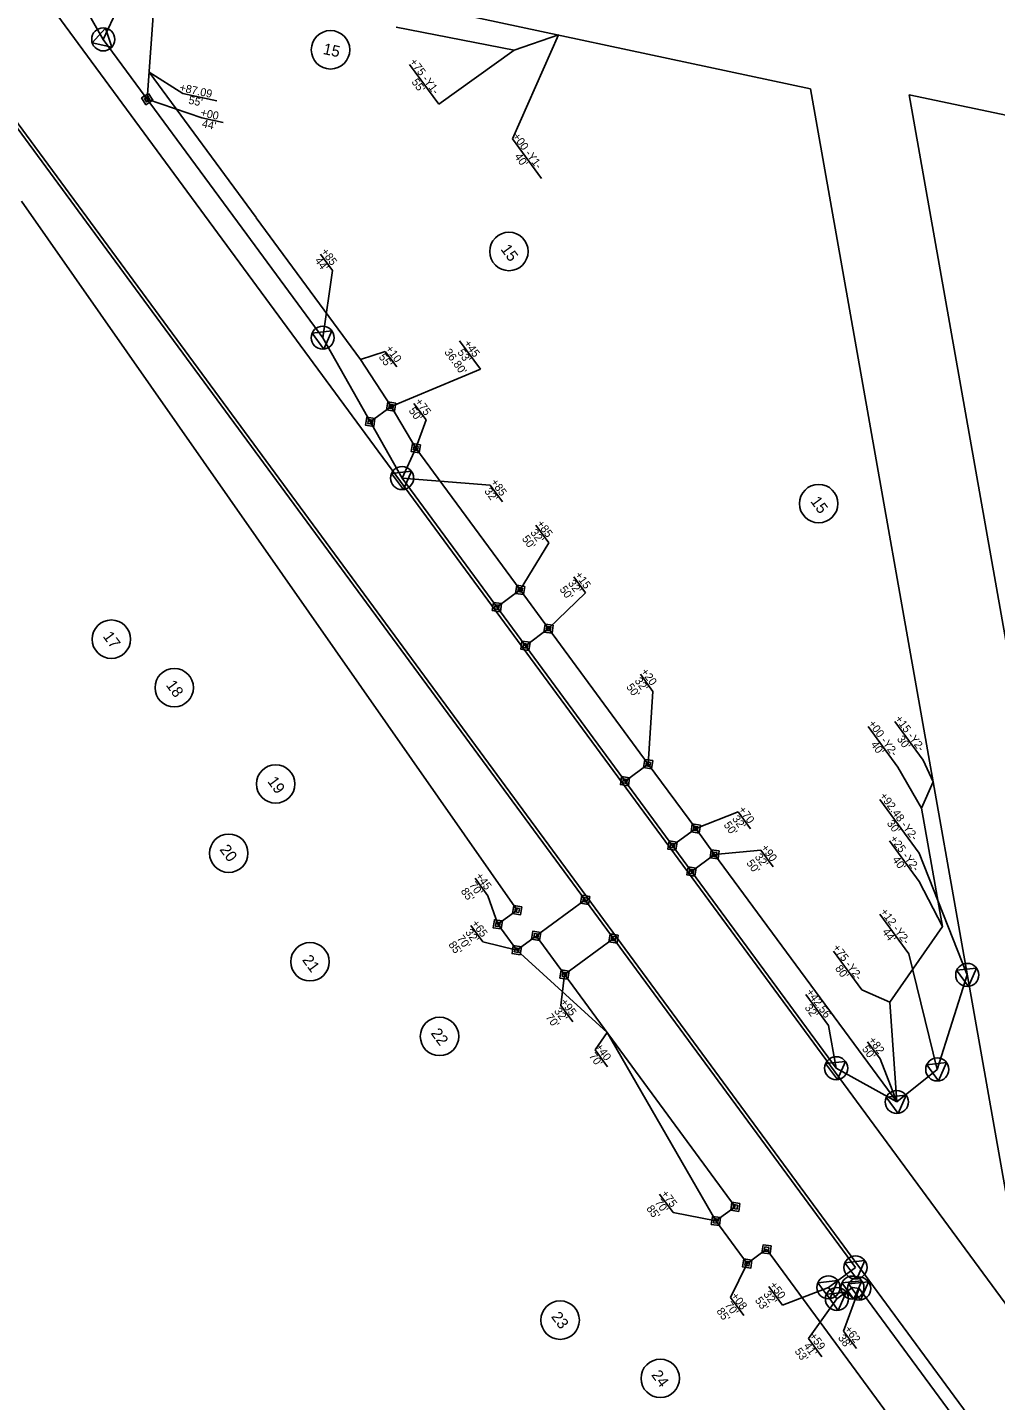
# Model space of a CAD drawing. Extents: x 1762160 to 1765875, y 710174 to 712931.
# Drawn here: x 1763351 to 1763955, y 711555 to 712412 of the extents above; entities that cross this region are included whole.
import ezdxf

# ---------------------------------------------------------------- set-up
doc = ezdxf.new("R2010")
doc.units = 0
for name, color, linetype in [('Exist Building', 7, 'Continuous'), ('Exist Building Foundations', 7, 'Continuous'), ('Exist Other Culture Area Outline', 7, 'Continuous'), ('Exist Other Culture Fence Line', 7, 'Continuous'), ('Exist Other Culture Located Object CELL', 7, 'Continuous'), ('Exist Other Culture Sign CELL', 7, 'Continuous'), ('Exist Roads Curbs', 7, 'Continuous'), ('Exist Roads EOP Other', 7, 'Continuous'), ('Exist Roads Soil', 7, 'Continuous'), ('Exist Structure Minor Head and End Wall', 7, 'Continuous'), ('Exist Utilities Other Pole CELL', 7, 'Continuous'), ('Exist Utilities Other Pole With Base CELL', 7, 'Continuous'), ('Exist Vegetation Shrub CELL', 7, 'Continuous'), ('Exist Vegetation Tree CELL', 7, 'Continuous'), ('Exist Vegetation Woods Line', 7, 'Continuous')]:
    doc.layers.add(name, color=color, linetype=linetype)

msp = doc.modelspace()

# ---------------------------------------------------------------- linework, layer by layer
at = {"layer": 'Exist Building'}
for p, q in [((1763658.25, 712060.86), (1763643.74, 712050.2)), ((1763658.25, 712060.86), (1763676.02, 712036.69)), ((1763676.02, 712036.69), (1763661.52, 712026.03)), ((1763738.22, 711952.1), (1763723.71, 711941.44)), ((1763738.22, 711952.1), (1763767.83, 711911.81))]:
    msp.add_line(p, q, dxfattribs=at)
at = {"layer": 'Exist Building Foundations'}
for p, q in [((1763430.66, 712441.3), (1763425.35, 712367.49)), ((1763346.94, 712303.63), (1763656.35, 711860.87)), ((1763564.68, 712165.84), (1763577.73, 712175.43)), ((1763577.73, 712175.43), (1763593.09, 712149.49)), ((1763593.09, 712149.49), (1763584.51, 712130.77)), ((1763767.83, 711911.81), (1763779.68, 711895.7)), ((1763779.68, 711895.7), (1763765.18, 711885.04)), ((1763644.26, 711851.99), (1763656.35, 711860.87)), ((1763644.26, 711851.99), (1763656.11, 711835.87)), ((1763656.11, 711835.87), (1763667.77, 711844.45)), ((1763685.96, 711820.59), (1763792.59, 711675.57)), ((1763780.5, 711666.68), (1763792.59, 711675.57)), ((1763780.5, 711666.68), (1763800.05, 711640.1)), ((1763800.05, 711640.1), (1763812.14, 711648.98)), ((1763812.14, 711648.98), (1763911.06, 711514.43))]:
    msp.add_line(p, q, dxfattribs=at)
at = {"layer": 'Exist Other Culture Area Outline'}
for p, q in [((1763397.92, 712404.8), (1763424.78, 712462.47)), ((1763397.92, 712404.8), (1763484.59, 712286.92)), ((1763336.69, 712359.78), (1763423.36, 712241.91)), ((1763484.59, 712286.92), (1763534.94, 712218.44)), ((1763423.36, 712241.91), (1763867.63, 711637.65)), ((1763534.94, 712218.44), (1763584.51, 712130.77)), ((1763584.51, 712130.77), (1763855.55, 711762.12)), ((1763937.38, 711820.38), (1763918.69, 711761.33)), ((1763855.55, 711762.12), (1763893.42, 711741.01)), ((1763893.42, 711741.01), (1763918.69, 711761.33)), ((1763850.71, 711625.21), (1763867.63, 711637.65)), ((1763856.04, 711617.96), (1763850.71, 711625.21)), ((1763856.04, 711617.96), (1763865.71, 711625.07)), ((1763865.71, 711625.07), (1763869.91, 711624.43)), ((1763869.91, 711624.43), (1763927.96, 711545.48))]:
    msp.add_line(p, q, dxfattribs=at)
at = {"layer": 'Exist Other Culture Fence Line'}
for p, q in [((1763425.35, 712367.49), (1763459.44, 712355.72)), ((1763459.44, 712355.72), (1763472.82, 712352.84)), ((1763620.42, 712216.41), (1763633.38, 712198.77)), ((1763577.73, 712175.43), (1763633.38, 712198.77)), ((1763591.95, 712177.39), (1763599.5, 712167.11)), ((1763593.09, 712149.49), (1763599.5, 712167.11)), ((1763808.52, 711898.42), (1763779.68, 711895.7)), ((1763808.52, 711898.42), (1763816.3, 711887.83)), ((1763630.17, 711880.73), (1763638.14, 711869.88)), ((1763638.14, 711869.88), (1763644.26, 711851.99)), ((1763745.3, 711683.34), (1763753.72, 711671.88)), ((1763753.72, 711671.88), (1763780.5, 711666.68)), ((1763789.65, 711618.89), (1763800.05, 711640.1)), ((1763789.65, 711618.89), (1763797.85, 711607.73))]:
    msp.add_line(p, q, dxfattribs=at)
at = {"layer": 'Exist Other Culture Located Object CELL'}
for p, q in [((1763682.11, 712407.58), (1763653.38, 712342.68)), ((1763654.53, 712398.13), (1763607.38, 712364.28)), ((1763589.13, 712389.13), (1763607.38, 712364.28)), ((1763447.55, 712370.98), (1763426.57, 712384.41)), ((1763447.55, 712370.98), (1763468.89, 712366.39)), ((1763653.38, 712342.68), (1763671.66, 712317.8)), ((1763558.61, 712204.82), (1763574.04, 712209.87)), ((1763574.04, 712209.87), (1763581.19, 712200.15)), ((1763875.52, 711975.53), (1763894.14, 711950.19)), ((1763892.14, 711978.74), (1763909.86, 711954.62)), ((1763894.14, 711950.19), (1763908.82, 711924.52)), ((1763909.86, 711954.62), (1763916.06, 711941.04)), ((1763888.83, 711904.08), (1763907.45, 711878.73)), ((1763907.45, 711878.73), (1763921.87, 711850.67)), ((1763853.89, 711835.13), (1763871.57, 711811.07)), ((1763871.57, 711811.07), (1763889.13, 711803.35)), ((1763705.02, 711773.57), (1763712.62, 711784.33)), ((1763705.02, 711773.57), (1763712.79, 711763))]:
    msp.add_line(p, q, dxfattribs=at)
at = {"layer": 'Exist Other Culture Sign CELL'}
for p, q in [((1763794.37, 711922.22), (1763767.83, 711911.81)), ((1763794.37, 711922.22), (1763802.16, 711911.63)), ((1763627.45, 711851.34), (1763634.95, 711841.14)), ((1763634.95, 711841.14), (1763656.11, 711835.87)), ((1763683.58, 711801.35), (1763685.96, 711820.59)), ((1763683.58, 711801.35), (1763691.15, 711791.05))]:
    msp.add_line(p, q, dxfattribs=at)
at = {"layer": 'Exist Roads Curbs'}
for p, q in [((1763397.92, 712404.8), (1763397.92, 712404.8)), ((1763425.35, 712367.49), (1763425.35, 712367.49)), ((1763534.94, 712218.44), (1763534.94, 712218.44)), ((1763577.73, 712175.43), (1763577.73, 712175.43)), ((1763564.68, 712165.84), (1763564.68, 712165.84)), ((1763593.09, 712149.49), (1763593.09, 712149.49)), ((1763584.51, 712130.77), (1763584.51, 712130.77)), ((1763658.25, 712060.86), (1763658.25, 712060.86)), ((1763643.74, 712050.2), (1763643.74, 712050.2)), ((1763676.02, 712036.69), (1763676.02, 712036.69)), ((1763661.52, 712026.03), (1763661.52, 712026.03)), ((1763738.22, 711952.1), (1763738.22, 711952.1)), ((1763723.71, 711941.44), (1763723.71, 711941.44)), ((1763767.83, 711911.81), (1763767.83, 711911.81)), ((1763753.33, 711901.15), (1763753.33, 711901.15)), ((1763779.68, 711895.7), (1763779.68, 711895.7)), ((1763765.18, 711885.04), (1763765.18, 711885.04)), ((1763698.81, 711867.27), (1763698.81, 711867.27)), ((1763656.35, 711860.87), (1763656.35, 711860.87)), ((1763644.26, 711851.99), (1763644.26, 711851.99)), ((1763668.19, 711844.76), (1763668.19, 711844.76)), ((1763716.58, 711843.1), (1763716.58, 711843.1)), ((1763656.11, 711835.87), (1763656.11, 711835.87)), ((1763685.96, 711820.59), (1763685.96, 711820.59)), ((1763937.38, 711820.38), (1763937.38, 711820.38)), ((1763855.55, 711762.12), (1763855.55, 711762.12)), ((1763918.69, 711761.33), (1763918.69, 711761.33)), ((1763893.42, 711741.01), (1763893.42, 711741.01)), ((1763792.59, 711675.57), (1763792.59, 711675.57)), ((1763780.5, 711666.68), (1763780.5, 711666.68)), ((1763812.14, 711648.98), (1763812.14, 711648.98)), ((1763800.05, 711640.1), (1763800.05, 711640.1)), ((1763867.63, 711637.65), (1763867.63, 711637.65)), ((1763850.71, 711625.21), (1763850.71, 711625.21)), ((1763865.71, 711625.07), (1763865.71, 711625.07)), ((1763869.91, 711624.43), (1763869.91, 711624.43)), ((1763856.04, 711617.96), (1763856.04, 711617.96))]:
    msp.add_line(p, q, dxfattribs=at)
for points in [[(1763391.06, 712402.59), (1763399.44, 712411.84), (1763403.28, 712399.96)], [(1763528.34, 712221.35), (1763540.74, 712222.71), (1763535.74, 712211.27)], [(1763577.91, 712133.67), (1763590.31, 712135.03), (1763585.31, 712123.6)], [(1763930.78, 711823.28), (1763943.18, 711824.64), (1763938.18, 711813.21)], [(1763848.95, 711765.03), (1763861.35, 711766.39), (1763856.35, 711754.96)], [(1763912.09, 711764.23), (1763924.49, 711765.59), (1763919.49, 711754.16)], [(1763886.81, 711743.92), (1763899.22, 711745.28), (1763894.22, 711733.84)], [(1763861.03, 711640.56), (1763873.43, 711641.92), (1763868.43, 711630.48)], [(1763844.11, 711628.12), (1763856.51, 711629.48), (1763851.51, 711618.05)], [(1763859.11, 711627.97), (1763871.51, 711629.33), (1763866.51, 711617.9)], [(1763863.3, 711627.34), (1763875.71, 711628.69), (1763870.71, 711617.26)], [(1763849.44, 711620.87), (1763861.85, 711622.23), (1763856.84, 711610.79)]]:
    msp.add_lwpolyline(points, close=True, dxfattribs=at)
for centre in [(1763397.92, 712404.8), (1763534.94, 712218.44), (1763584.51, 712130.77), (1763937.38, 711820.38), (1763855.55, 711762.12), (1763918.69, 711761.33), (1763893.42, 711741.01), (1763867.63, 711637.65), (1763850.71, 711625.21), (1763865.71, 711625.07), (1763856.04, 711617.96), (1763869.91, 711624.43)]:
    msp.add_circle(centre, 7.2, dxfattribs=at)
at = {"layer": 'Exist Roads EOP Other'}
for p, q in [((1763580.9, 712412.49), (1763654.53, 712398.13)), ((1763654.53, 712398.13), (1763682.11, 712407.58)), ((1763426.57, 712384.41), (1763493.45, 712293.44)), ((1763493.47, 712293.42), (1763558.61, 712204.82)), ((1763558.61, 712204.82), (1763577.73, 712175.43)), ((1763593.09, 712149.49), (1763658.25, 712060.86)), ((1763676.02, 712036.69), (1763738.22, 711952.1)), ((1763916.06, 711941.04), (1763908.82, 711924.52)), ((1763908.82, 711924.52), (1763921.87, 711850.67)), ((1763779.68, 711895.7), (1763893.42, 711741.01)), ((1763921.87, 711850.67), (1763889.13, 711803.35)), ((1763656.11, 711835.87), (1763712.62, 711784.33)), ((1763889.13, 711803.35), (1763893.42, 711741.01)), ((1763712.62, 711784.33), (1763780.5, 711666.68))]:
    msp.add_line(p, q, dxfattribs=at)
at = {"layer": 'Exist Roads Soil'}
for p, q in [((1763767.83, 711911.81), (1763753.33, 711901.15)), ((1763668.19, 711844.76), (1763698.81, 711867.27)), ((1763668.19, 711844.76), (1763685.96, 711820.59)), ((1763685.96, 711820.59), (1763716.58, 711843.1))]:
    msp.add_line(p, q, dxfattribs=at)
at = {"layer": 'Exist Structure Minor Head and End Wall'}
for points in [[(1763426.12, 712371.01), (1763428.87, 712366.73), (1763424.59, 712363.97), (1763421.83, 712368.26)], [(1763425.73, 712369.25), (1763427.11, 712367.11), (1763424.97, 712365.73), (1763423.59, 712367.87)], [(1763580.63, 712177.57), (1763579.86, 712172.53), (1763574.83, 712173.3), (1763575.6, 712178.33)], [(1763579.18, 712176.5), (1763578.8, 712173.98), (1763576.28, 712174.37), (1763576.67, 712176.88)], [(1763567.58, 712167.97), (1763566.81, 712162.94), (1763561.78, 712163.71), (1763562.55, 712168.74)], [(1763566.13, 712166.9), (1763565.75, 712164.39), (1763563.23, 712164.77), (1763563.61, 712167.29)], [(1763595.99, 712151.62), (1763595.22, 712146.59), (1763590.19, 712147.36), (1763590.95, 712152.39)], [(1763594.54, 712150.55), (1763594.15, 712148.04), (1763591.64, 712148.42), (1763592.02, 712150.94)], [(1763661.15, 712062.99), (1763660.38, 712057.96), (1763655.35, 712058.73), (1763656.11, 712063.76)], [(1763659.7, 712061.93), (1763659.31, 712059.41), (1763656.8, 712059.8), (1763657.18, 712062.31)], [(1763646.65, 712052.33), (1763645.88, 712047.3), (1763640.84, 712048.07), (1763641.61, 712053.1)], [(1763645.2, 712051.27), (1763644.81, 712048.75), (1763642.29, 712049.13), (1763642.68, 712051.65)], [(1763678.92, 712038.82), (1763678.15, 712033.79), (1763673.12, 712034.56), (1763673.89, 712039.59)], [(1763677.47, 712037.76), (1763677.08, 712035.24), (1763674.57, 712035.63), (1763674.95, 712038.14)], [(1763664.42, 712028.16), (1763663.65, 712023.13), (1763658.62, 712023.9), (1763659.38, 712028.93)], [(1763662.97, 712027.1), (1763662.58, 712024.58), (1763660.07, 712024.96), (1763660.45, 712027.48)], [(1763741.12, 711954.23), (1763740.35, 711949.2), (1763735.32, 711949.97), (1763736.08, 711955)], [(1763739.67, 711953.16), (1763739.28, 711950.65), (1763736.77, 711951.03), (1763737.15, 711953.55)], [(1763726.61, 711943.57), (1763725.85, 711938.53), (1763720.81, 711939.3), (1763721.58, 711944.34)], [(1763725.16, 711942.5), (1763724.78, 711939.98), (1763722.26, 711940.37), (1763722.65, 711942.89)], [(1763770.74, 711913.95), (1763769.97, 711908.91), (1763764.93, 711909.68), (1763765.7, 711914.72)], [(1763769.28, 711912.88), (1763768.9, 711910.36), (1763766.38, 711910.75), (1763766.77, 711913.26)], [(1763756.23, 711903.28), (1763755.46, 711898.25), (1763750.43, 711899.02), (1763751.2, 711904.05)], [(1763754.78, 711902.22), (1763754.4, 711899.7), (1763751.88, 711900.09), (1763752.27, 711902.6)], [(1763782.58, 711897.83), (1763781.81, 711892.8), (1763776.78, 711893.57), (1763777.55, 711898.6)], [(1763781.13, 711896.77), (1763780.75, 711894.25), (1763778.23, 711894.64), (1763778.62, 711897.15)], [(1763768.08, 711887.17), (1763767.31, 711882.14), (1763762.28, 711882.91), (1763763.05, 711887.94)], [(1763766.63, 711886.1), (1763766.25, 711883.59), (1763763.73, 711883.97), (1763764.11, 711886.49)], [(1763659.25, 711863), (1763658.48, 711857.97), (1763653.44, 711858.74), (1763654.21, 711863.77)], [(1763701.71, 711869.4), (1763700.94, 711864.37), (1763695.91, 711865.14), (1763696.68, 711870.17)], [(1763700.26, 711868.33), (1763699.87, 711865.82), (1763697.36, 711866.2), (1763697.74, 711868.72)], [(1763657.8, 711861.94), (1763657.41, 711859.42), (1763654.89, 711859.81), (1763655.28, 711862.32)], [(1763647.16, 711854.12), (1763646.39, 711849.09), (1763641.36, 711849.86), (1763642.13, 711854.89)], [(1763645.71, 711853.05), (1763645.33, 711850.54), (1763642.81, 711850.92), (1763643.19, 711853.44)], [(1763671.09, 711846.89), (1763670.32, 711841.86), (1763665.29, 711842.63), (1763666.06, 711847.66)], [(1763659.01, 711838.01), (1763658.24, 711832.97), (1763653.21, 711833.74), (1763653.98, 711838.77)], [(1763669.64, 711845.82), (1763669.26, 711843.31), (1763666.74, 711843.69), (1763667.13, 711846.21)], [(1763719.48, 711845.23), (1763718.71, 711840.2), (1763713.68, 711840.97), (1763714.45, 711846)], [(1763718.03, 711844.16), (1763717.64, 711841.65), (1763715.13, 711842.03), (1763715.51, 711844.55)], [(1763657.56, 711836.94), (1763657.17, 711834.42), (1763654.66, 711834.81), (1763655.04, 711837.32)], [(1763688.86, 711822.72), (1763688.09, 711817.69), (1763683.06, 711818.46), (1763683.83, 711823.49)], [(1763687.41, 711821.65), (1763687.03, 711819.14), (1763684.51, 711819.52), (1763684.9, 711822.04)], [(1763795.49, 711677.7), (1763794.72, 711672.67), (1763789.69, 711673.44), (1763790.46, 711678.47)], [(1763794.04, 711676.63), (1763793.65, 711674.12), (1763791.14, 711674.5), (1763791.52, 711677.02)], [(1763783.4, 711668.81), (1763782.64, 711663.78), (1763777.6, 711664.55), (1763778.37, 711669.58)], [(1763781.95, 711667.75), (1763781.57, 711665.23), (1763779.05, 711665.62), (1763779.44, 711668.13)], [(1763815.04, 711651.11), (1763814.27, 711646.08), (1763809.24, 711646.85), (1763810, 711651.88)], [(1763813.59, 711650.05), (1763813.2, 711647.53), (1763810.69, 711647.92), (1763811.07, 711650.43)], [(1763802.95, 711642.23), (1763802.18, 711637.19), (1763797.15, 711637.96), (1763797.92, 711643)], [(1763801.5, 711641.16), (1763801.12, 711638.65), (1763798.6, 711639.03), (1763798.99, 711641.55)]]:
    msp.add_lwpolyline(points, close=True, dxfattribs=at)
at = {"layer": 'Exist Utilities Other Pole CELL'}
for p, q in [((1763379.24, 712437.55), (1763397.92, 712404.8)), ((1763533.56, 712270.67), (1763541.1, 712260.42)), ((1763639.59, 712126.31), (1763647.2, 712115.95)), ((1763882.79, 711930), (1763907.47, 711896.42)), ((1763937.38, 711820.38), (1763907.47, 711896.42)), ((1763882.79, 711858.43), (1763901, 711833.64)), ((1763901, 711833.64), (1763918.69, 711761.33)), ((1763836.67, 711808.06), (1763850.79, 711788.84)), ((1763850.79, 711788.84), (1763855.55, 711762.12)), ((1763875.07, 711778.68), (1763882.92, 711767.99)), ((1763882.92, 711767.99), (1763893.42, 711741.01)), ((1763813.48, 711625.65), (1763821.99, 711614.07)), ((1763850.71, 711625.21), (1763821.99, 711614.07)), ((1763869.91, 711624.43), (1763860.2, 711597.82)), ((1763856.04, 711617.96), (1763838.32, 711593.2)), ((1763838.32, 711593.2), (1763846.65, 711581.87)), ((1763860.2, 711597.82), (1763868.16, 711586.98))]:
    msp.add_line(p, q, dxfattribs=at)
for points in [[(1763541.1, 712260.42), (1763534.94, 712218.44)], [(1763639.59, 712126.31), (1763584.51, 712130.77)]]:
    msp.add_lwpolyline(points, dxfattribs=at)
at = {"layer": 'Exist Utilities Other Pole With Base CELL'}
for p, q in [((1763369.65, 712474.23), (1763839.56, 712374)), ((1763977.6, 711592.75), (1763350.79, 712445.09)), ((1764075.06, 711358.95), (1763321.14, 712384.13)), ((1763839.56, 712374), (1763977.6, 711592.75)), ((1763901.16, 712370.18), (1764041.9, 711573.67)), ((1763901.16, 712370.18), (1764006.49, 712347.86))]:
    msp.add_line(p, q, dxfattribs=at)
at = {"layer": 'Exist Vegetation Shrub CELL'}
for p, q in [((1763668, 712101.32), (1763676.09, 712090.31)), ((1763676.09, 712090.31), (1763658.25, 712060.86)), ((1763691.69, 712069.1), (1763699.05, 712059.08)), ((1763699.05, 712059.08), (1763676.02, 712036.69)), ((1763733.35, 712008.19), (1763741.18, 711997.53)), ((1763741.18, 711997.53), (1763738.22, 711952.1))]:
    msp.add_line(p, q, dxfattribs=at)
at = {"layer": 'Exist Vegetation Tree CELL'}
for centre in [(1763539.83, 712398.29), (1763651.23, 712272.31), (1763844.63, 712114.82), (1763402.99, 712030.1), (1763442.26, 711999.82), (1763505.59, 711939.69), (1763476.3, 711896.41), (1763527.02, 711828.59), (1763607.9, 711781.97), (1763683.2, 711604.74), (1763745.72, 711568.35)]:
    msp.add_circle(centre, 12, dxfattribs=at)

# ---------------------------------------------------------------- texts
at = {"layer": 'Exist Other Culture Fence Line'}
for s, rotation, p in [('+00', 347.86389, (1763458.37, 712356.86)), ("44'", 347.86389, (1763459.23, 712350.02)), ('+45', 306.30835, (1763622.77, 712214.85)), ("36.80'", 306.30835, (1763610.66, 712209.38)), ("53'", 306.30835, (1763618.83, 712209.24)), ("50'", 306.30835, (1763588.39, 712172.83)), ('+75', 306.30835, (1763592.33, 712178.44)), ('+90', 306.313, (1763808.36, 711899.77)), ("50'", 306.313, (1763799.24, 711890.23)), ("32'", 306.313, (1763804.47, 711894.08)), ('+45', 306.313, (1763630.11, 711882.09)), ("85'", 306.313, (1763620.92, 711872.63)), ("70'", 306.313, (1763626.16, 711876.48)), ('+75', 306.313, (1763745.98, 711683.82)), ("85'", 306.313, (1763736.8, 711674.36)), ("70'", 306.313, (1763742.04, 711678.21)), ("70'", 306.313, (1763785.81, 711614.14)), ('+08', 306.313, (1763789.69, 711619.83)), ("85'", 306.313, (1763780.57, 711610.29))]:
    msp.add_text(s, height=5, rotation=rotation, dxfattribs=at).set_placement(p)
at = {"layer": 'Exist Other Culture Located Object CELL'}
for s, rotation, p in [('+75 -Y1-', 306.30835, (1763588.99, 712390.73)), ("55'", 306.30835, (1763590.17, 712378.13)), ('+87.09', 347.86389, (1763445.19, 712372.53)), ("55'", 347.86389, (1763450.85, 712364.67)), ('+00 -Y1-', 306.30835, (1763653.24, 712344.19)), ("40'", 306.30835, (1763654.43, 712331.59)), ("55'", 306.30835, (1763569.69, 712206.35)), ('+10', 306.30835, (1763573.93, 712211.56)), ('+00 -Y2-', 306.30835, (1763875.31, 711977.33)), ('+15 -Y2-', 306.30835, (1763892.03, 711980.33)), ("30'", 306.30835, (1763893.22, 711967.73)), ("40'", 306.30835, (1763876.85, 711964.25)), ('+25 -Y2-', 306.30835, (1763888.83, 711905.37)), ("40'", 306.30835, (1763890.37, 711892.29)), ('+75 -Y2-', 306.30835, (1763853.08, 711837.43)), ("80'", 306.30835, (1763854.62, 711824.35)), ("70'", 306.30835, (1763700.93, 711769.68)), ('+40', 306.30835, (1763704.82, 711775.38))]:
    msp.add_text(s, height=5, rotation=rotation, dxfattribs=at).set_placement(p)
at = {"layer": 'Exist Other Culture Sign CELL'}
for s, p in [('+70', (1763794.22, 711923.58)), ("50'", (1763785.09, 711914.04)), ("32'", (1763790.33, 711917.89)), ("32'", (1763623.67, 711846.96)), ('+65', (1763627.62, 711852.57)), ("85'", (1763613.2, 711839.26)), ("70'", (1763618.44, 711843.11)), ('+95', (1763683.09, 711803.41)), ("70'", (1763673.91, 711793.95)), ("32'", (1763679.15, 711797.8))]:
    msp.add_text(s, height=5, rotation=306.313, dxfattribs=at).set_placement(p)
at = {"layer": 'Exist Utilities Other Pole CELL'}
for s, p in [("44'", (1763529.72, 712266.58)), ('+85', (1763533.66, 712272.19)), ("32'", (1763635.63, 712122.52)), ('+85', (1763639.58, 712128.13)), ('+92.48 -Y2-', (1763882.44, 711932.15)), ("30'", (1763886.91, 711915.09)), ('+12 -Y2-', (1763882.84, 711859.83)), ("44'", (1763884.03, 711847.24)), ('+42.56', (1763836.58, 711809.58)), ("32'", (1763835.61, 711799.91)), ('+82', (1763875.44, 711779.6)), ("50'", (1763871.4, 711774.13)), ('+50', (1763813.71, 711626.6)), ("53'", (1763804.58, 711617.06)), ("32'", (1763809.82, 711620.9)), ('+62', (1763860.48, 711599.08)), ("41'", (1763834.96, 711588.57)), ('+59', (1763838.52, 711594.71)), ("38'", (1763856.44, 711593.61)), ("53'", (1763829.37, 711585.21))]:
    msp.add_text(s, height=5, rotation=306.30835, dxfattribs=at).set_placement(p)
at = {"layer": 'Exist Vegetation Shrub CELL'}
for s, p in [("50'", (1763659.08, 712092.84)), ("32'", (1763664.32, 712096.69)), ('+85', (1763668.26, 712102.29)), ('+15', (1763692.13, 712070.17)), ("50'", (1763682.59, 712061.19)), ("32'", (1763687.83, 712065.04)), ('+20', (1763733.33, 712009.78)), ("50'", (1763724.21, 712000.24)), ("32'", (1763729.45, 712004.09))]:
    msp.add_text(s, height=5, rotation=306.313, dxfattribs=at).set_placement(p)
at = {"layer": 'Exist Vegetation Woods Line'}
for s, rotation, p in [('15', 347.86389, (1763534.76, 712395.75)), ('15', 306.30835, (1763645.75, 712273.71)), ('15', 306.30835, (1763839.16, 712116.22)), ('17', 306.30835, (1763397.39, 712031.84)), ('18', 306.30835, (1763436.76, 712001.41)), ('19', 306.30835, (1763500.12, 711941.24)), ('20', 306.30835, (1763470.3, 711898.69)), ('21', 306.30835, (1763521.84, 711829.75)), ('22', 306.30835, (1763602.12, 711783.94)), ('23', 306.30835, (1763677.29, 711606.9)), ('24', 306.30835, (1763739.83, 711570.47))]:
    msp.add_text(s, height=7, rotation=rotation, dxfattribs=at).set_placement(p)

doc.saveas('drawing.dxf')
